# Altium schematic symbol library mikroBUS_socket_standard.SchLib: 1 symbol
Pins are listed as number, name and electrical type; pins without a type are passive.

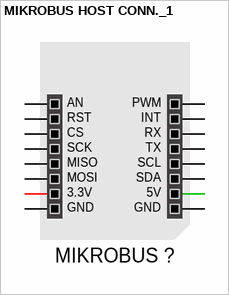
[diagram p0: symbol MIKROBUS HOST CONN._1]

## MIKROBUS HOST CONN._1
designator MIKROBUS ?, comment MIKROBUS HOST CONN.  (value not drawn)
mikroBUS Host Socket
footprint MIKROBUS HOST CONN. SMD
footprint MIKROBUS HOST CONN. TH
pins: 1 AN, 2 RST, 3 CS, 4 SCK, 5 MISO, 6 MOSI, 7 3.3V, 8 GND, 9 GND, 10 5V, 11 SDA, 12 SCL, 13 TX, 14 RX, 15 INT, 16 PWM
